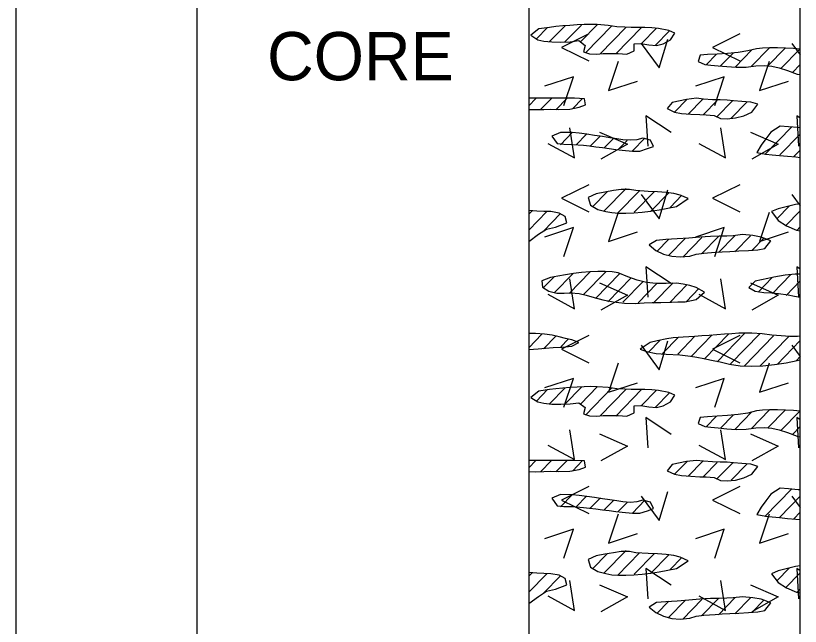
# Model space of a CAD drawing. Extents: x -0.01 to 0.83, y -0.63 to 1.27.
# Drawn here: x 0.725 to 0.8333, y -0.1744 to -0.0901 of the extents above; entities that cross this region are included whole.
import ezdxf

# ---------------------------------------------------------------- set-up
doc = ezdxf.new("R2010")
doc.units = 0

msp = doc.modelspace()

# ---------------------------------------------------------------- linework, layer by layer
for points in [[(0.725, 1.22083), (0.725, -0.62183)], [(0.75, 1.22083), (0.75, -0.62183)], [(0.75, 1.22083), (0.75, -0.62183)], [(0.79583, 1.22083), (0.79583, -0.62183)], [(0.725, 1.20833), (0.725, -0.62183)], [(0.83333, -0.62183), (0.83333, 1.13843)], [(0.79844, -0.09172), (0.79691, -0.09329)], [(0.79871, -0.09366), (0.80085, -0.09147)], [(0.80083, -0.09371), (0.80311, -0.09137)], [(0.80534, -0.09129), (0.80299, -0.09371)], [(0.80367, -0.09522), (0.80732, -0.09148)], [(0.80571, -0.09534), (0.80924, -0.09172)], [(0.81142, -0.09171), (0.80785, -0.09536)], [(0.81141, -0.09393), (0.81348, -0.0918)], [(0.80412, -0.09258), (0.80038, -0.09446), (0.80412, -0.09633)], [(0.81528, -0.09217), (0.81331, -0.09419)], [(0.82496, -0.09258), (0.82121, -0.09446), (0.82496, -0.09633)], [(0.81134, -0.09393), (0.81384, -0.0973), (0.81503, -0.0933)], [(0.83217, -0.09393), (0.83333, -0.09549)], [(0.82233, -0.09702), (0.82408, -0.09524)], [(0.82433, -0.09719), (0.82666, -0.0948)], [(0.82909, -0.09452), (0.82656, -0.09711)], [(0.82885, -0.09699), (0.83122, -0.09456)], [(0.83325, -0.09469), (0.83065, -0.09735)], [(0.82035, -0.09685), (0.82176, -0.0954)], [(0.80818, -0.09642), (0.80687, -0.10042), (0.81087, -0.0991)], [(0.82901, -0.09642), (0.8277, -0.10042), (0.8317, -0.0991)], [(0.83333, -0.09682), (0.83227, -0.09791)], [(0.80069, -0.1025), (0.802, -0.0985), (0.798, -0.09981)], [(0.82152, -0.1025), (0.82284, -0.0985), (0.81884, -0.09981)], [(0.79583, -0.10252), (0.79681, -0.10152)], [(0.79898, -0.1015), (0.79747, -0.10305)], [(0.80116, -0.10148), (0.79959, -0.10309)], [(0.80328, -0.10152), (0.80188, -0.10296)], [(0.8177, -0.10162), (0.81596, -0.10341)], [(0.81988, -0.10161), (0.81785, -0.10368)], [(0.82185, -0.1018), (0.81997, -0.10372)], [(0.824, -0.10181), (0.82178, -0.10409)], [(0.82601, -0.10196), (0.82378, -0.10424)], [(0.81551, -0.10622), (0.81201, -0.10391), (0.81226, -0.1081)], [(0.83333, -0.10423), (0.83284, -0.10391), (0.83309, -0.1081)], [(0.79847, -0.10771), (0.80215, -0.10971), (0.80153, -0.10558)], [(0.80562, -0.10616), (0.80946, -0.10784), (0.80581, -0.10991)], [(0.8193, -0.10771), (0.82299, -0.10971), (0.82236, -0.10558)], [(0.82645, -0.10616), (0.83029, -0.10784), (0.82664, -0.10991)], [(0.83217, -0.10541), (0.82844, -0.10923)], [(0.80188, -0.10618), (0.8002, -0.10791)], [(0.8038, -0.10643), (0.80237, -0.10789)], [(0.80575, -0.10665), (0.80429, -0.10814)], [(0.80758, -0.10698), (0.80627, -0.10832)], [(0.81188, -0.107), (0.81016, -0.10876)], [(0.83333, -0.10643), (0.83052, -0.10931)], [(0.80941, -0.10731), (0.80816, -0.1086)], [(0.83333, -0.10864), (0.83245, -0.10954)], [(0.80412, -0.11342), (0.80038, -0.11529), (0.80412, -0.11717)], [(0.82496, -0.11342), (0.82121, -0.11529), (0.82496, -0.11717)], [(0.80465, -0.11646), (0.80667, -0.11439)], [(0.80626, -0.11703), (0.80928, -0.11393)], [(0.80809, -0.11736), (0.81111, -0.11426)], [(0.81041, -0.1172), (0.81318, -0.11436)], [(0.81134, -0.11476), (0.81384, -0.11813), (0.81503, -0.11413)], [(0.81264, -0.11712), (0.81518, -0.11452)], [(0.83217, -0.11476), (0.83333, -0.11632)], [(0.81536, -0.11655), (0.81699, -0.11488)], [(0.8301, -0.11812), (0.83184, -0.11634)], [(0.7963, -0.11701), (0.79583, -0.11749)], [(0.79834, -0.11714), (0.79583, -0.1197)], [(0.79786, -0.11984), (0.80023, -0.11741)], [(0.80818, -0.11725), (0.80687, -0.12125), (0.81087, -0.11994)], [(0.82901, -0.11725), (0.8277, -0.12125), (0.8317, -0.11994)], [(0.83131, -0.1191), (0.83333, -0.11702)], [(0.80069, -0.12333), (0.802, -0.11933), (0.798, -0.12064)], [(0.82152, -0.12333), (0.82284, -0.11933), (0.81884, -0.12064)], [(0.83285, -0.11972), (0.83333, -0.11924)], [(0.81519, -0.12094), (0.81354, -0.12264)], [(0.81514, -0.1232), (0.81748, -0.12081)], [(0.81709, -0.12342), (0.81974, -0.1207)], [(0.8197, -0.12296), (0.82203, -0.12057)], [(0.82202, -0.1228), (0.8243, -0.12046)], [(0.82431, -0.12267), (0.82644, -0.12047)], [(0.82663, -0.1225), (0.82834, -0.12075)], [(0.79933, -0.12835), (0.80195, -0.12566)], [(0.80142, -0.12842), (0.8043, -0.12546)], [(0.80653, -0.12539), (0.8034, -0.1286)], [(0.81551, -0.12706), (0.81201, -0.12474), (0.81226, -0.12893)], [(0.83333, -0.12507), (0.83284, -0.12474), (0.83309, -0.12893)], [(0.79938, -0.12608), (0.79786, -0.12763)], [(0.79847, -0.12854), (0.80215, -0.13054), (0.80153, -0.12641)], [(0.80506, -0.12911), (0.8084, -0.12569)], [(0.80997, -0.12629), (0.80675, -0.12959)], [(0.8193, -0.12854), (0.82299, -0.13054), (0.82236, -0.12641)], [(0.82751, -0.12824), (0.82945, -0.12625)], [(0.83203, -0.12582), (0.82949, -0.12842)], [(0.83138, -0.1287), (0.83333, -0.1267)], [(0.80562, -0.12699), (0.80946, -0.12868), (0.80581, -0.13074)], [(0.81164, -0.1268), (0.80884, -0.12966)], [(0.81353, -0.12707), (0.81094, -0.12973)], [(0.81303, -0.12979), (0.81579, -0.12697)], [(0.81534, -0.12964), (0.81768, -0.12724)], [(0.8176, -0.12953), (0.81934, -0.12775)], [(0.82645, -0.12699), (0.83029, -0.12868), (0.82664, -0.13074)], [(0.83333, -0.12892), (0.83333, -0.12891)], [(0.79765, -0.13406), (0.79583, -0.13593)], [(0.7996, -0.13428), (0.79786, -0.13606)], [(0.80412, -0.13425), (0.80038, -0.13613), (0.80412, -0.138)], [(0.81829, -0.13708), (0.82114, -0.13416)], [(0.82004, -0.1375), (0.82346, -0.134)], [(0.82496, -0.13425), (0.82121, -0.13613), (0.82496, -0.138)], [(0.82569, -0.13392), (0.82184, -0.13787)], [(0.82775, -0.13402), (0.8237, -0.13817)], [(0.82964, -0.1343), (0.82557, -0.13847)], [(0.8013, -0.13476), (0.80027, -0.13581)], [(0.81134, -0.13559), (0.81384, -0.13897), (0.81503, -0.13497)], [(0.81392, -0.13492), (0.81235, -0.13652)], [(0.8143, -0.13674), (0.8165, -0.13449)], [(0.8164, -0.13681), (0.81879, -0.13435)], [(0.83173, -0.13437), (0.82774, -0.13846)], [(0.83333, -0.13494), (0.83012, -0.13824)], [(0.83217, -0.13559), (0.83333, -0.13715)], [(0.83281, -0.13769), (0.83333, -0.13716)], [(0.80818, -0.13808), (0.80687, -0.14208), (0.81087, -0.14077)], [(0.82901, -0.13808), (0.8277, -0.14208), (0.8317, -0.14077)], [(0.80069, -0.14416), (0.802, -0.14016), (0.798, -0.14148)], [(0.82152, -0.14416), (0.82284, -0.14016), (0.81884, -0.14148)], [(0.79844, -0.14172), (0.79691, -0.14329)], [(0.79871, -0.14366), (0.80085, -0.14147)], [(0.80083, -0.14371), (0.80311, -0.14137)], [(0.80534, -0.14129), (0.80299, -0.14371)], [(0.80367, -0.14522), (0.80732, -0.14148)], [(0.80571, -0.14534), (0.80924, -0.14172)], [(0.81142, -0.14171), (0.80785, -0.14536)], [(0.81141, -0.14393), (0.81348, -0.1418)], [(0.81528, -0.14217), (0.81331, -0.14419)], [(0.82433, -0.14719), (0.82666, -0.1448)], [(0.82909, -0.14452), (0.82656, -0.14711)], [(0.82885, -0.14699), (0.83122, -0.14456)], [(0.83325, -0.14469), (0.83065, -0.14735)], [(0.81551, -0.14789), (0.81201, -0.14558), (0.81226, -0.14976)], [(0.82035, -0.14685), (0.82176, -0.1454)], [(0.82233, -0.14702), (0.82408, -0.14524)], [(0.83333, -0.1459), (0.83284, -0.14558), (0.83309, -0.14976)], [(0.79847, -0.14937), (0.80215, -0.15137), (0.80153, -0.14725)], [(0.8193, -0.14937), (0.82299, -0.15137), (0.82236, -0.14725)], [(0.83333, -0.14682), (0.83227, -0.14791)], [(0.80562, -0.14783), (0.80946, -0.14951), (0.80581, -0.15157)], [(0.82645, -0.14783), (0.83029, -0.14951), (0.82664, -0.15157)], [(0.79583, -0.15252), (0.79681, -0.15152)], [(0.79898, -0.1515), (0.79747, -0.15305)], [(0.80116, -0.15148), (0.79959, -0.15309)], [(0.80328, -0.15152), (0.80188, -0.15296)], [(0.8177, -0.15162), (0.81596, -0.15341)], [(0.81988, -0.15161), (0.81785, -0.15368)], [(0.82185, -0.1518), (0.81997, -0.15372)], [(0.824, -0.15181), (0.82178, -0.15409)], [(0.82601, -0.15196), (0.82378, -0.15424)], [(0.80412, -0.15508), (0.80038, -0.15696), (0.80412, -0.15883)], [(0.81134, -0.15643), (0.81384, -0.1598), (0.81503, -0.1558)], [(0.82496, -0.15508), (0.82121, -0.15696), (0.82496, -0.15883)], [(0.83217, -0.15541), (0.82844, -0.15923)], [(0.80188, -0.15618), (0.8002, -0.15791)], [(0.8038, -0.15643), (0.80237, -0.15789)], [(0.80575, -0.15665), (0.80429, -0.15814)], [(0.80758, -0.15698), (0.80627, -0.15832)], [(0.81188, -0.157), (0.81016, -0.15876)], [(0.83333, -0.15643), (0.83052, -0.15931)], [(0.83217, -0.15643), (0.83333, -0.15799)], [(0.80941, -0.15731), (0.80816, -0.1586)], [(0.80818, -0.15892), (0.80687, -0.16292), (0.81087, -0.1616)], [(0.82901, -0.15892), (0.8277, -0.16292), (0.8317, -0.1616)], [(0.83333, -0.15864), (0.83245, -0.15954)], [(0.80069, -0.165), (0.802, -0.161), (0.798, -0.16231)], [(0.82152, -0.165), (0.82284, -0.161), (0.81884, -0.16231)], [(0.80465, -0.16646), (0.80667, -0.16439)], [(0.80626, -0.16703), (0.80928, -0.16393)], [(0.80809, -0.16736), (0.81111, -0.16426)], [(0.81041, -0.1672), (0.81318, -0.16436)], [(0.81264, -0.16712), (0.81518, -0.16452)], [(0.81536, -0.16655), (0.81699, -0.16488)], [(0.81551, -0.16872), (0.81201, -0.16641), (0.81226, -0.1706)], [(0.8301, -0.16812), (0.83184, -0.16634)], [(0.83333, -0.16673), (0.83284, -0.16641), (0.83309, -0.1706)], [(0.7963, -0.16701), (0.79583, -0.16749)], [(0.79834, -0.16714), (0.79583, -0.1697)], [(0.79786, -0.16984), (0.80023, -0.16741)], [(0.83131, -0.1691), (0.83333, -0.16702)], [(0.79847, -0.17021), (0.80215, -0.17221), (0.80153, -0.16808)], [(0.80562, -0.16866), (0.80946, -0.17034), (0.80581, -0.17241)], [(0.8193, -0.17021), (0.82299, -0.17221), (0.82236, -0.16808)], [(0.82645, -0.16866), (0.83029, -0.17034), (0.82664, -0.17241)], [(0.83285, -0.16972), (0.83333, -0.16924)], [(0.81519, -0.17094), (0.81354, -0.17264)], [(0.81514, -0.1732), (0.81748, -0.17081)], [(0.81709, -0.17342), (0.81974, -0.1707)], [(0.8197, -0.17296), (0.82203, -0.17057)], [(0.82202, -0.1728), (0.8243, -0.17046)], [(0.82431, -0.17267), (0.82644, -0.17047)], [(0.82663, -0.1725), (0.82834, -0.17075)]]:
    msp.add_lwpolyline(points)
for points in [[(0.79708, -0.09341), (0.79794, -0.09358), (0.79904, -0.0937), (0.80028, -0.09373), (0.80156, -0.09368), (0.80274, -0.09352), (0.80361, -0.09418), (0.80338, -0.09508), (0.80422, -0.09535), (0.80517, -0.09537), (0.80613, -0.09531), (0.8072, -0.09528), (0.80818, -0.09531), (0.80939, -0.09539), (0.81037, -0.09492), (0.81038, -0.09397), (0.8113, -0.09391), (0.81244, -0.0941), (0.81346, -0.0942), (0.81438, -0.09395), (0.81539, -0.09341), (0.81601, -0.09249), (0.81517, -0.09212), (0.81374, -0.09184), (0.81285, -0.09175), (0.81187, -0.09169), (0.81, -0.09169), (0.8091, -0.09167), (0.808, -0.0916), (0.80678, -0.09144), (0.8053, -0.09131), (0.80443, -0.0913), (0.80349, -0.09131), (0.80251, -0.09136), (0.80152, -0.09142), (0.80054, -0.0915), (0.79959, -0.09159), (0.7987, -0.09169), (0.79722, -0.09191), (0.79614, -0.09279)], [(0.83241, -0.09462), (0.83129, -0.09456), (0.83017, -0.09452), (0.8291, -0.09452), (0.82811, -0.09456), (0.82728, -0.09465), (0.82608, -0.09495), (0.82476, -0.09517), (0.8233, -0.09531), (0.82183, -0.09539), (0.82051, -0.09545), (0.81951, -0.09555), (0.81922, -0.09642), (0.82013, -0.09683), (0.82097, -0.09689), (0.822, -0.09698), (0.82318, -0.09711), (0.82448, -0.0972), (0.82584, -0.09718), (0.82719, -0.09701), (0.82836, -0.09695), (0.8294, -0.09703), (0.83043, -0.09726), (0.83156, -0.09765), (0.83291, -0.09814), (0.83333, -0.09822), (0.83333, -0.0947)], [(0.79583, -0.10304), (0.79676, -0.10305), (0.79792, -0.10303), (0.79882, -0.10299), (0.79992, -0.10303), (0.80151, -0.10299), (0.80282, -0.10273), (0.80367, -0.10241), (0.80354, -0.10157), (0.80216, -0.10149), (0.79583, -0.10149)], [(0.81822, -0.10368), (0.81944, -0.10374), (0.82033, -0.10378), (0.82145, -0.10385), (0.82229, -0.10426), (0.82324, -0.10431), (0.82438, -0.1042), (0.82555, -0.10391), (0.82662, -0.10341), (0.82749, -0.10231), (0.82651, -0.10201), (0.82524, -0.10191), (0.82413, -0.10184), (0.82324, -0.10174), (0.82226, -0.10172), (0.82121, -0.1017), (0.81995, -0.1016), (0.81902, -0.10149), (0.81761, -0.10163), (0.81566, -0.10207), (0.81496, -0.10291), (0.81598, -0.1034), (0.81695, -0.10357)], [(0.83305, -0.10554), (0.83171, -0.10542), (0.83054, -0.10532), (0.82925, -0.10614), (0.82857, -0.10706), (0.82792, -0.10794), (0.82735, -0.10897), (0.82858, -0.1092), (0.82945, -0.1093), (0.83045, -0.10939), (0.83155, -0.10949), (0.83272, -0.10959), (0.83333, -0.10964), (0.83333, -0.10555)], [(0.80066, -0.10784), (0.80188, -0.10785), (0.80339, -0.10797), (0.80423, -0.10807), (0.8051, -0.10818), (0.806, -0.1083), (0.80692, -0.10842), (0.80784, -0.10854), (0.80875, -0.10865), (0.81014, -0.10879), (0.81119, -0.10878), (0.81222, -0.10843), (0.81308, -0.10815), (0.81267, -0.10725), (0.8116, -0.107), (0.81075, -0.1072), (0.80989, -0.10728), (0.80885, -0.1072), (0.80799, -0.10709), (0.80703, -0.10694), (0.806, -0.10678), (0.80492, -0.10661), (0.80384, -0.10646), (0.8028, -0.10632), (0.80182, -0.10623), (0.8002, -0.10622), (0.79901, -0.1067), (0.79974, -0.10774)], [(0.81233, -0.11434), (0.81063, -0.11423), (0.80977, -0.11409), (0.8086, -0.11409), (0.80755, -0.11423), (0.80632, -0.11443), (0.80513, -0.11467), (0.80403, -0.11519), (0.80436, -0.11625), (0.80536, -0.11682), (0.80647, -0.11712), (0.8073, -0.11727), (0.80824, -0.11735), (0.80926, -0.11735), (0.81035, -0.1173), (0.81149, -0.1172), (0.81267, -0.11705), (0.81386, -0.11687), (0.81506, -0.11666), (0.81625, -0.11642), (0.81783, -0.11534), (0.81673, -0.11484), (0.81585, -0.11464), (0.8148, -0.11448), (0.81361, -0.11438)], [(0.79583, -0.12125), (0.79719, -0.12026), (0.79831, -0.11956), (0.79951, -0.11929), (0.80111, -0.11869), (0.80086, -0.11781), (0.80002, -0.11733), (0.79889, -0.11714), (0.79791, -0.11711), (0.79694, -0.11705), (0.79583, -0.11697)], [(0.83265, -0.11616), (0.83136, -0.11647), (0.83028, -0.11674), (0.82934, -0.11714), (0.83026, -0.11834), (0.83142, -0.1191), (0.83279, -0.11968), (0.83333, -0.11978), (0.83333, -0.11607)], [(0.82537, -0.12031), (0.82408, -0.12046), (0.82319, -0.12052), (0.82214, -0.12054), (0.82091, -0.12058), (0.81947, -0.12067), (0.81792, -0.12079), (0.81632, -0.12091), (0.81475, -0.121), (0.81348, -0.1211), (0.81247, -0.12174), (0.81337, -0.1225), (0.81444, -0.12301), (0.81561, -0.1233), (0.81675, -0.1234), (0.81807, -0.12329), (0.81896, -0.12301), (0.82003, -0.12287), (0.82157, -0.12275), (0.82253, -0.12269), (0.82362, -0.12263), (0.82483, -0.12257), (0.82618, -0.1225), (0.82745, -0.1224), (0.82842, -0.12222), (0.82927, -0.12117), (0.82791, -0.12065), (0.82679, -0.12045)], [(0.79885, -0.12622), (0.79763, -0.12668), (0.79773, -0.12758), (0.79859, -0.1281), (0.7997, -0.1284), (0.80074, -0.12839), (0.80165, -0.12837), (0.80281, -0.12845), (0.80377, -0.12866), (0.80486, -0.12901), (0.80606, -0.12931), (0.80751, -0.12958), (0.80905, -0.12977), (0.81052, -0.1298), (0.81177, -0.12974), (0.81289, -0.1297), (0.81408, -0.12967), (0.81553, -0.12963), (0.81642, -0.1296), (0.81745, -0.12957), (0.81897, -0.12929), (0.82011, -0.12826), (0.81896, -0.12759), (0.8181, -0.12732), (0.81717, -0.12713), (0.81626, -0.12702), (0.81479, -0.12708), (0.81343, -0.12708), (0.8121, -0.12693), (0.8108, -0.12662), (0.80953, -0.12616), (0.8082, -0.12561), (0.80736, -0.12545), (0.8064, -0.12538), (0.80536, -0.12538), (0.80427, -0.12544), (0.80314, -0.12555), (0.80201, -0.12569), (0.8009, -0.12586), (0.79984, -0.12604)], [(0.83263, -0.12577), (0.83126, -0.12591), (0.82969, -0.12618), (0.82883, -0.12635), (0.82712, -0.12676), (0.82623, -0.12763), (0.82708, -0.12812), (0.82831, -0.12831), (0.82941, -0.12837), (0.83033, -0.12846), (0.83165, -0.12864), (0.83253, -0.12879), (0.83333, -0.12893), (0.83333, -0.12578)], [(0.79583, -0.13618), (0.79715, -0.13607), (0.79814, -0.13599), (0.79922, -0.13592), (0.80039, -0.13583), (0.80179, -0.13571), (0.80275, -0.13519), (0.80179, -0.13485), (0.80091, -0.13464), (0.80003, -0.13442), (0.79909, -0.13421), (0.79803, -0.13405), (0.79677, -0.13395), (0.79583, -0.13397)], [(0.82816, -0.13842), (0.82978, -0.13825), (0.83137, -0.138), (0.8329, -0.13769), (0.83333, -0.13759), (0.83333, -0.13435), (0.83295, -0.13438), (0.83188, -0.13436), (0.83071, -0.1343), (0.82938, -0.1342), (0.82807, -0.13403), (0.82662, -0.13391), (0.82576, -0.13391), (0.82484, -0.13394), (0.82387, -0.13399), (0.82286, -0.13406), (0.82182, -0.13414), (0.82077, -0.13422), (0.81973, -0.1343), (0.81872, -0.13438), (0.81715, -0.13447), (0.81579, -0.13457), (0.81491, -0.1347), (0.81357, -0.13497), (0.8126, -0.13519), (0.81121, -0.13611), (0.8121, -0.13647), (0.81345, -0.13671), (0.81479, -0.1368), (0.81668, -0.13691), (0.81818, -0.13711), (0.81905, -0.13725), (0.82, -0.13743), (0.82107, -0.13765), (0.82225, -0.1379), (0.82357, -0.13819), (0.82501, -0.13842), (0.82656, -0.13849)], [(0.79708, -0.14341), (0.79794, -0.14358), (0.79904, -0.1437), (0.80028, -0.14373), (0.80156, -0.14368), (0.80274, -0.14352), (0.80361, -0.14418), (0.80338, -0.14508), (0.80422, -0.14535), (0.80517, -0.14537), (0.80613, -0.14531), (0.8072, -0.14528), (0.80818, -0.14531), (0.80939, -0.14539), (0.81037, -0.14492), (0.81038, -0.14397), (0.8113, -0.14391), (0.81244, -0.1441), (0.81346, -0.1442), (0.81438, -0.14395), (0.81539, -0.14341), (0.81601, -0.14249), (0.81517, -0.14212), (0.81374, -0.14184), (0.81285, -0.14175), (0.81187, -0.14169), (0.81, -0.14169), (0.8091, -0.14167), (0.808, -0.1416), (0.80678, -0.14144), (0.8053, -0.14131), (0.80443, -0.1413), (0.80349, -0.14131), (0.80251, -0.14136), (0.80152, -0.14142), (0.80054, -0.1415), (0.79959, -0.14159), (0.7987, -0.14169), (0.79722, -0.14191), (0.79614, -0.14279)], [(0.83241, -0.14462), (0.83129, -0.14456), (0.83017, -0.14452), (0.8291, -0.14452), (0.82811, -0.14456), (0.82728, -0.14465), (0.82608, -0.14495), (0.82476, -0.14517), (0.8233, -0.14531), (0.82183, -0.14539), (0.82051, -0.14545), (0.81951, -0.14555), (0.81922, -0.14641), (0.82013, -0.14683), (0.82097, -0.14689), (0.822, -0.14698), (0.82318, -0.14711), (0.82448, -0.1472), (0.82584, -0.14718), (0.82719, -0.14701), (0.82836, -0.14695), (0.8294, -0.14703), (0.83043, -0.14726), (0.83156, -0.14765), (0.83291, -0.14814), (0.83333, -0.14822), (0.83333, -0.1447)], [(0.79583, -0.15304), (0.79676, -0.15305), (0.79792, -0.15303), (0.79882, -0.15299), (0.79992, -0.15303), (0.80151, -0.15299), (0.80282, -0.15273), (0.80367, -0.15241), (0.80354, -0.15157), (0.80216, -0.15149), (0.79583, -0.15149)], [(0.81822, -0.15368), (0.81944, -0.15374), (0.82033, -0.15378), (0.82145, -0.15385), (0.82229, -0.15426), (0.82324, -0.15431), (0.82438, -0.1542), (0.82555, -0.15391), (0.82662, -0.15341), (0.82749, -0.15231), (0.82651, -0.15201), (0.82524, -0.15191), (0.82413, -0.15184), (0.82324, -0.15174), (0.82226, -0.15172), (0.82121, -0.1517), (0.81995, -0.1516), (0.81902, -0.15149), (0.81761, -0.15163), (0.81566, -0.15207), (0.81496, -0.15291), (0.81598, -0.1534), (0.81695, -0.15357)], [(0.83305, -0.15554), (0.83171, -0.15542), (0.83054, -0.15532), (0.82925, -0.15614), (0.82857, -0.15706), (0.82792, -0.15794), (0.82735, -0.15897), (0.82858, -0.1592), (0.82945, -0.1593), (0.83045, -0.15939), (0.83155, -0.15949), (0.83272, -0.15959), (0.83333, -0.15964), (0.83333, -0.15555)], [(0.80066, -0.15784), (0.80188, -0.15785), (0.80339, -0.15797), (0.80423, -0.15807), (0.8051, -0.15818), (0.806, -0.1583), (0.80692, -0.15842), (0.80784, -0.15854), (0.80875, -0.15865), (0.81014, -0.15879), (0.81119, -0.15878), (0.81222, -0.15843), (0.81308, -0.15815), (0.81267, -0.15725), (0.8116, -0.157), (0.81075, -0.1572), (0.80989, -0.15728), (0.80885, -0.1572), (0.80799, -0.15709), (0.80703, -0.15694), (0.806, -0.15678), (0.80492, -0.15661), (0.80384, -0.15646), (0.8028, -0.15632), (0.80182, -0.15623), (0.8002, -0.15622), (0.79901, -0.1567), (0.79974, -0.15774)], [(0.81233, -0.16434), (0.81063, -0.16423), (0.80977, -0.16409), (0.8086, -0.16409), (0.80755, -0.16423), (0.80632, -0.16443), (0.80513, -0.16467), (0.80403, -0.16519), (0.80436, -0.16625), (0.80536, -0.16682), (0.80647, -0.16712), (0.8073, -0.16727), (0.80824, -0.16735), (0.80926, -0.16735), (0.81035, -0.1673), (0.81149, -0.1672), (0.81267, -0.16705), (0.81386, -0.16687), (0.81506, -0.16666), (0.81625, -0.16642), (0.81783, -0.16534), (0.81673, -0.16484), (0.81585, -0.16464), (0.8148, -0.16448), (0.81361, -0.16438)], [(0.83265, -0.16616), (0.83136, -0.16647), (0.83028, -0.16674), (0.82934, -0.16714), (0.83026, -0.16834), (0.83142, -0.1691), (0.83279, -0.16968), (0.83333, -0.16978), (0.83333, -0.16607)], [(0.79583, -0.17125), (0.79719, -0.17026), (0.79831, -0.16956), (0.79951, -0.16929), (0.80111, -0.16869), (0.80086, -0.16781), (0.80002, -0.16733), (0.79889, -0.16714), (0.79791, -0.16711), (0.79694, -0.16705), (0.79583, -0.16697)], [(0.82537, -0.17031), (0.82408, -0.17046), (0.82319, -0.17052), (0.82214, -0.17054), (0.82091, -0.17058), (0.81947, -0.17067), (0.81792, -0.17079), (0.81632, -0.17091), (0.81475, -0.171), (0.81348, -0.1711), (0.81247, -0.17174), (0.81337, -0.1725), (0.81444, -0.17301), (0.81561, -0.1733), (0.81675, -0.1734), (0.81807, -0.17329), (0.81896, -0.17301), (0.82003, -0.17287), (0.82157, -0.17275), (0.82253, -0.17269), (0.82362, -0.17263), (0.82483, -0.17257), (0.82618, -0.1725), (0.82745, -0.1724), (0.82842, -0.17222), (0.82927, -0.17117), (0.82791, -0.17065), (0.82679, -0.17045)]]:
    msp.add_lwpolyline(points, close=True)

# ---------------------------------------------------------------- texts
msp.add_text('CORE', height=0.006667).set_placement((0.75971, -0.099))

doc.saveas('drawing.dxf')
